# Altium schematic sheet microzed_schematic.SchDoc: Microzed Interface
size A3; Organization: Altium Limited; Address1: L3, 12a Rodborough Rd; Address2: Frenchs Forest; Address3: NSW; Address4: Australia 2086; DocumentNumber: 2; SheetNumber: 2; SheetTotal: 8
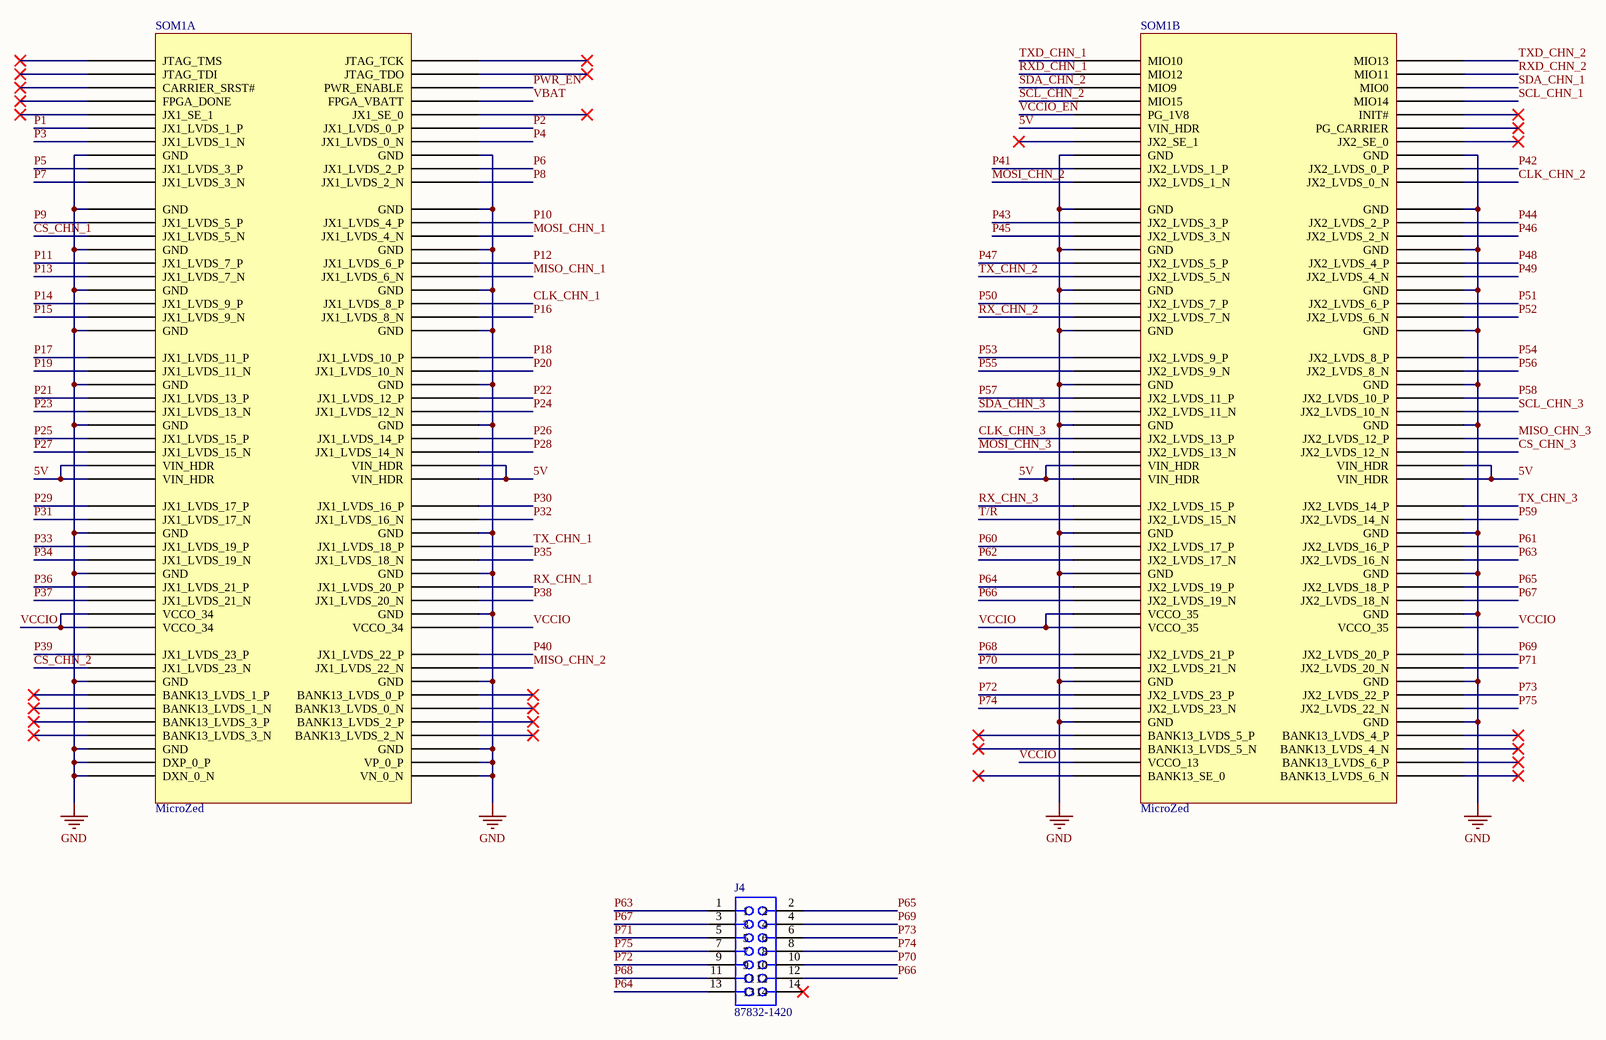
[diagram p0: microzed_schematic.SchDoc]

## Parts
J4  87832-1420  [SAMTEC_TSW-107-05-F-D]
SOM1  MicroZed  [MicroZedSOM]  (parts A,B of 2)

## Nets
GND: SOM1.JX1-15(GND) SOM1.JX1-16(GND) SOM1.JX1-21(GND) SOM1.JX1-22(GND) SOM1.JX1-27(GND) SOM1.JX1-28(GND) SOM1.JX1-33(GND) SOM1.JX1-34(GND) SOM1.JX1-39(GND) SOM1.JX1-40(GND) SOM1.JX1-45(GND) SOM1.JX1-46(GND) SOM1.JX1-51(GND) SOM1.JX1-52(GND) SOM1.JX1-65(GND) SOM1.JX1-66(GND) SOM1.JX1-71(GND) SOM1.JX1-72(GND) SOM1.JX1-77(GND) SOM1.JX1-85(GND) SOM1.JX1-86(GND) SOM1.JX1-95(GND) SOM1.JX1-96(GND) SOM1.JX1-97(VP_0_P) SOM1.JX1-98(DXP_0_P) SOM1.JX1-99(VN_0_N) SOM1.JX1-100(DXN_0_N) SOM1.JX2-15(GND) SOM1.JX2-16(GND) SOM1.JX2-21(GND) SOM1.JX2-22(GND) SOM1.JX2-27(GND) SOM1.JX2-28(GND) SOM1.JX2-33(GND) SOM1.JX2-34(GND) SOM1.JX2-39(GND) SOM1.JX2-40(GND) SOM1.JX2-45(GND) SOM1.JX2-46(GND) SOM1.JX2-51(GND) SOM1.JX2-52(GND) SOM1.JX2-65(GND) SOM1.JX2-66(GND) SOM1.JX2-71(GND) SOM1.JX2-72(GND) SOM1.JX2-77(GND) SOM1.JX2-85(GND) SOM1.JX2-86(GND) SOM1.JX2-91(GND) SOM1.JX2-92(GND)
5V: SOM1.JX1-57(VIN_HDR) SOM1.JX1-58(VIN_HDR) SOM1.JX1-59(VIN_HDR) SOM1.JX1-60(VIN_HDR) SOM1.JX2-12(VIN_HDR) SOM1.JX2-57(VIN_HDR) SOM1.JX2-58(VIN_HDR) SOM1.JX2-59(VIN_HDR) SOM1.JX2-60(VIN_HDR)
CLK_CHN_1: SOM1.JX1-35(JX1_LVDS_8_P)
CLK_CHN_2: SOM1.JX2-19(JX2_LVDS_0_N)
CLK_CHN_3: SOM1.JX2-54(JX2_LVDS_13_P)
CS_CHN_1: SOM1.JX1-26(JX1_LVDS_5_N)
CS_CHN_2: SOM1.JX1-84(JX1_LVDS_23_N)
CS_CHN_3: SOM1.JX2-55(JX2_LVDS_12_N)
MISO_CHN_1: SOM1.JX1-31(JX1_LVDS_6_N)
MISO_CHN_2: SOM1.JX1-83(JX1_LVDS_22_N)
MISO_CHN_3: SOM1.JX2-53(JX2_LVDS_12_P)
MOSI_CHN_1: SOM1.JX1-25(JX1_LVDS_4_N)
MOSI_CHN_2: SOM1.JX2-20(JX2_LVDS_1_N)
MOSI_CHN_3: SOM1.JX2-56(JX2_LVDS_13_N)
P1: SOM1.JX1-12(JX1_LVDS_1_P)
P2: SOM1.JX1-11(JX1_LVDS_0_P)
P3: SOM1.JX1-14(JX1_LVDS_1_N)
P4: SOM1.JX1-13(JX1_LVDS_0_N)
P5: SOM1.JX1-18(JX1_LVDS_3_P)
P6: SOM1.JX1-17(JX1_LVDS_2_P)
P7: SOM1.JX1-20(JX1_LVDS_3_N)
P8: SOM1.JX1-19(JX1_LVDS_2_N)
P9: SOM1.JX1-24(JX1_LVDS_5_P)
P10: SOM1.JX1-23(JX1_LVDS_4_P)
P11: SOM1.JX1-30(JX1_LVDS_7_P)
P12: SOM1.JX1-29(JX1_LVDS_6_P)
P13: SOM1.JX1-32(JX1_LVDS_7_N)
P14: SOM1.JX1-36(JX1_LVDS_9_P)
P15: SOM1.JX1-38(JX1_LVDS_9_N)
P16: SOM1.JX1-37(JX1_LVDS_8_N)
P17: SOM1.JX1-42(JX1_LVDS_11_P)
P18: SOM1.JX1-41(JX1_LVDS_10_P)
P19: SOM1.JX1-44(JX1_LVDS_11_N)
P20: SOM1.JX1-43(JX1_LVDS_10_N)
P21: SOM1.JX1-48(JX1_LVDS_13_P)
P22: SOM1.JX1-47(JX1_LVDS_12_P)
P23: SOM1.JX1-50(JX1_LVDS_13_N)
P24: SOM1.JX1-49(JX1_LVDS_12_N)
P25: SOM1.JX1-54(JX1_LVDS_15_P)
P26: SOM1.JX1-53(JX1_LVDS_14_P)
P27: SOM1.JX1-56(JX1_LVDS_15_N)
P28: SOM1.JX1-55(JX1_LVDS_14_N)
P29: SOM1.JX1-62(JX1_LVDS_17_P)
P30: SOM1.JX1-61(JX1_LVDS_16_P)
P31: SOM1.JX1-64(JX1_LVDS_17_N)
P32: SOM1.JX1-63(JX1_LVDS_16_N)
P33: SOM1.JX1-68(JX1_LVDS_19_P)
P34: SOM1.JX1-70(JX1_LVDS_19_N)
P35: SOM1.JX1-69(JX1_LVDS_18_N)
P36: SOM1.JX1-74(JX1_LVDS_21_P)
P37: SOM1.JX1-76(JX1_LVDS_21_N)
P38: SOM1.JX1-75(JX1_LVDS_20_N)
P39: SOM1.JX1-82(JX1_LVDS_23_P)
P40: SOM1.JX1-81(JX1_LVDS_22_P)
P41: SOM1.JX2-18(JX2_LVDS_1_P)
P42: SOM1.JX2-17(JX2_LVDS_0_P)
P43: SOM1.JX2-24(JX2_LVDS_3_P)
P44: SOM1.JX2-23(JX2_LVDS_2_P)
P45: SOM1.JX2-26(JX2_LVDS_3_N)
P46: SOM1.JX2-25(JX2_LVDS_2_N)
P47: SOM1.JX2-30(JX2_LVDS_5_P)
P48: SOM1.JX2-29(JX2_LVDS_4_P)
P49: SOM1.JX2-31(JX2_LVDS_4_N)
P50: SOM1.JX2-36(JX2_LVDS_7_P)
P51: SOM1.JX2-35(JX2_LVDS_6_P)
P52: SOM1.JX2-37(JX2_LVDS_6_N)
P53: SOM1.JX2-42(JX2_LVDS_9_P)
P54: SOM1.JX2-41(JX2_LVDS_8_P)
P55: SOM1.JX2-44(JX2_LVDS_9_N)
P56: SOM1.JX2-43(JX2_LVDS_8_N)
P57: SOM1.JX2-48(JX2_LVDS_11_P)
P58: SOM1.JX2-47(JX2_LVDS_10_P)
P59: SOM1.JX2-63(JX2_LVDS_14_N)
P60: SOM1.JX2-68(JX2_LVDS_17_P)
P61: SOM1.JX2-67(JX2_LVDS_16_P)
P62: SOM1.JX2-70(JX2_LVDS_17_N)
P63: J4.1 SOM1.JX2-69(JX2_LVDS_16_N)
P64: J4.13 SOM1.JX2-74(JX2_LVDS_19_P)
P65: J4.2 SOM1.JX2-73(JX2_LVDS_18_P)
P66: J4.12 SOM1.JX2-76(JX2_LVDS_19_N)
P67: J4.3 SOM1.JX2-75(JX2_LVDS_18_N)
P68: J4.11 SOM1.JX2-82(JX2_LVDS_21_P)
P69: J4.4 SOM1.JX2-81(JX2_LVDS_20_P)
P70: J4.10 SOM1.JX2-84(JX2_LVDS_21_N)
P71: J4.5 SOM1.JX2-83(JX2_LVDS_20_N)
P72: J4.9 SOM1.JX2-88(JX2_LVDS_23_P)
P73: J4.6 SOM1.JX2-87(JX2_LVDS_22_P)
P74: J4.8 SOM1.JX2-90(JX2_LVDS_23_N)
P75: J4.7 SOM1.JX2-89(JX2_LVDS_22_N)
PWR_EN: SOM1.JX1-5(PWR_ENABLE)
RX_CHN_1: SOM1.JX1-73(JX1_LVDS_20_P)
RX_CHN_2: SOM1.JX2-38(JX2_LVDS_7_N)
RX_CHN_3: SOM1.JX2-62(JX2_LVDS_15_P)
RXD_CHN_1: SOM1.JX2-4(MIO12)
RXD_CHN_2: SOM1.JX2-3(MIO11)
SCL_CHN_1: SOM1.JX2-7(MIO14)
SCL_CHN_2: SOM1.JX2-8(MIO15)
SCL_CHN_3: SOM1.JX2-49(JX2_LVDS_10_N)
SDA_CHN_1: SOM1.JX2-5(MIO0)
SDA_CHN_2: SOM1.JX2-6(MIO9)
SDA_CHN_3: SOM1.JX2-50(JX2_LVDS_11_N)
T/R: SOM1.JX2-64(JX2_LVDS_15_N)
TX_CHN_1: SOM1.JX1-67(JX1_LVDS_18_P)
TX_CHN_2: SOM1.JX2-32(JX2_LVDS_5_N)
TX_CHN_3: SOM1.JX2-61(JX2_LVDS_14_P)
TXD_CHN_1: SOM1.JX2-2(MIO10)
TXD_CHN_2: SOM1.JX2-1(MIO13)
VBAT: SOM1.JX1-7(FPGA_VBATT)
VCCIO: SOM1.JX1-78(VCCO_34) SOM1.JX1-79(VCCO_34) SOM1.JX1-80(VCCO_34) SOM1.JX2-78(VCCO_35) SOM1.JX2-79(VCCO_35) SOM1.JX2-80(VCCO_35) SOM1.JX2-98(VCCO_13)
VCCIO_EN: SOM1.JX2-10(PG_1V8)

Not connected (* = marked no-connect by the designer): J4 14*; SOM1 JX1-1(JTAG_TCK)* JX1-2(JTAG_TMS)* JX1-3(JTAG_TDO)* JX1-4(JTAG_TDI)* JX1-6(CARRIER_SRST#)* JX1-8(FPGA_DONE)* JX1-9(JX1_SE_0)* JX1-10(JX1_SE_1)* JX1-87(BANK13_LVDS_0_P)* JX1-88(BANK13_LVDS_1_P)* JX1-89(BANK13_LVDS_0_N)* JX1-90(BANK13_LVDS_1_N)* JX1-91(BANK13_LVDS_2_P)* JX1-92(BANK13_LVDS_3_P)* JX1-93(BANK13_LVDS_2_N)* JX1-94(BANK13_LVDS_3_N)* JX2-9(INIT#)* JX2-11(PG_CARRIER)* JX2-13(JX2_SE_0)* JX2-14(JX2_SE_1)* JX2-93(BANK13_LVDS_4_P)* JX2-94(BANK13_LVDS_5_P)* JX2-95(BANK13_LVDS_4_N)* JX2-96(BANK13_LVDS_5_N)* JX2-97(BANK13_LVDS_6_P)* JX2-99(BANK13_LVDS_6_N)* JX2-100(BANK13_SE_0)*

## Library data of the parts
J4 = 87832-1420: Connector Header Surface Mount 14 position 0.079 _2.00mm_; Manufacturer Part Number: TSW-107-05-F-D; MF: Molex
SOM1 = MicroZed_SOM: MicroZed SOM Carrier Footprint; Manufacturer Part Number: 61083-101400LF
